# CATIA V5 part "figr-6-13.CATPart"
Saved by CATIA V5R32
Part number: Part1
Bounding box of the stored display mesh (mm): x -25 to 25, y -75 to 75, z 0 to 20
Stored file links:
  D:\PROJECTS\Project 2022\CATIA V5 6R 2022\Resources\Part Files\c06_catia_v5_6r2022_prt\figr-6-13.CATPart
  C:\Program Files\Dassault Systemes\B13\intel_a\reffiles\standard\MetricThinPitch.txt
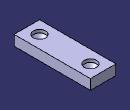
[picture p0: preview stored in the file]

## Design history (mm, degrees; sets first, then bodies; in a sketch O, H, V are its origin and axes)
Body1 (main body)
  Sketch1 on xy-plane, origin (0, 0, 0), H (1, 0, 0), V (0, 1, 0)
    line L1 (-25, 75) -> (25, 75)
    line L2 (25, 75) -> (25, -75)
    line L3 (25, -75) -> (-25, -75)
    line L4 (-25, -75) -> (-25, 75)
    axis line L5 (25, -75) -> (-25, 75)
    length L2 = 150
    length L3 = 50
    horizontal: L1 H, L3 H
    vertical: L2 V, L4 V
    midpoint: O L5
  Pad1: profile Sketch1, direction (0, 0, 1), length 20
  Sketch2 on face of Pad1, origin (-8.6664, -28.8348, 20), H (1, 0, 0), V (0, 1, 0)
    point P1 (8.6664, -21.1652)
    reference projected line E1 (-16.3336, -46.1652) -> (33.6664, -46.1652) from edge [face of Pad1 | face of Pad1]
    reference projected line E2 (-16.3336, 103.8348) -> (-16.3336, -46.1652) from edge [face of Pad1 | face of Pad1]
    distance P1 E1 = 25
    distance P1 E2 = 25
  Hole1: placed by Sketch2, at (0, -50, 20) direction (0, 0, -1), diameter 10.647, through (limit type 3), type CounterDrilledType, Diameter 10.647, DiameterThread 12, Pas 1.25, Profile a sketch, Sketch Sketch2, ThreadDepth 10, ThreadDescription "M12", Angle 90, Depth 6, Diameter 24
  Sketch3 on face of Pad1, origin (3.6925, 50.8892, 20), H (1, 0, 0), V (0, 1, 0)
    point P1 (-3.6925, -0.8892)
    reference projected line E1 (-28.6925, 24.1108) -> (-28.6925, -125.8892) from edge [face of Pad1 | face of Pad1]
    reference projected line E2 (21.3075, 24.1108) -> (-28.6925, 24.1108) from edge [face of Pad1 | face of Pad1]
    distance P1 E1 = 25
    distance E2 P1 = 25
  Hole2: placed by Sketch3, at (0, 50, 20) direction (0, 0, -1), diameter 10.647, through (limit type 3), type CounterDrilledType, Diameter 10.647, DiameterThread 11.7117, Pas 1, Profile a sketch, Sketch Sketch3, ThreadDepth 10, Angle 90, Depth 6, Diameter 24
